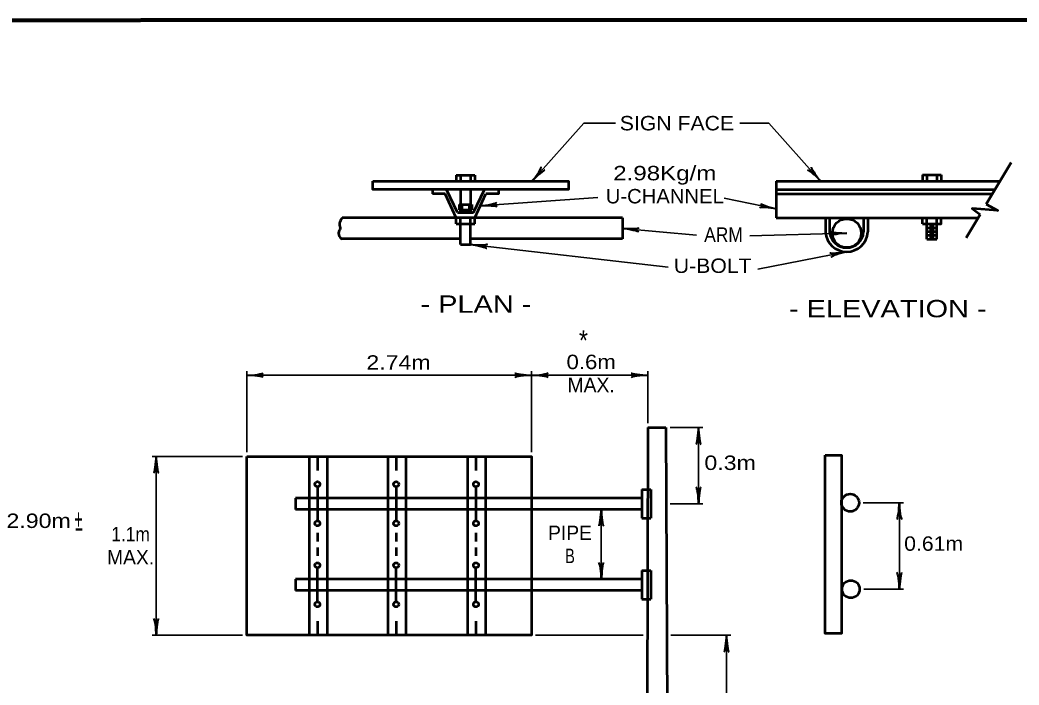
# Model space of a CAD drawing. Extents: x -274 to 582, y -298 to 246.
# Drawn here: x 154.4 to 362.2, y 101.7 to 240 of the extents above; entities that cross this region are included whole.
import ezdxf
from ezdxf.enums import TextEntityAlignment as Align

# ---------------------------------------------------------------- set-up
doc = ezdxf.new("R2010")
doc.units = 0
doc.header["$LTSCALE"] = 1.2
doc.layers.add('1', color=7, linetype='Continuous', lineweight=53)

msp = doc.modelspace()

# ---------------------------------------------------------------- linework, layer by layer
at = {"layer": '1', "lineweight": 35}
for p, q in [((271.669, 218.515), (260.903, 206.487)), ((271.669, 218.515), (278.267, 218.515)), ((304.099, 218.515), (310.143, 218.515)), ((310.143, 218.515), (320.909, 206.487)), ((250.141, 201.342), (274.617, 203.067)), ((311.68, 200.679), (300.87, 202.926)), ((279.711, 196.639), (295.114, 195.202)), ((326.39, 195.642), (306.205, 195.062)), ((248.108, 193.288), (289.218, 188.602)), ((326.35, 191.767), (307.89, 188.18)), ((201.538, 150.12), (201.538, 166.984)), ((260.772, 150.12), (260.772, 166.984)), ((284.987, 156.121), (284.987, 166.984)), ((260.772, 166.113), (201.538, 166.113)), ((260.772, 166.113), (284.987, 166.113)), ((289.606, 155.25), (296.404, 155.25)), ((295.533, 139.394), (295.533, 155.25)), ((200.667, 149.248), (181.834, 149.248)), ((182.705, 149.248), (182.705, 112.065)), ((289.606, 139.394), (296.404, 139.394)), ((329.795, 139.614), (338.185, 139.614)), ((337.314, 139.614), (337.314, 121.643)), ((275.307, 138.232), (275.307, 123.712)), ((329.919, 121.643), (338.185, 121.643)), ((200.667, 112.065), (181.834, 112.065)), ((261.643, 112.065), (283.997, 112.065)), ((289.785, 112.065), (302.229, 112.065)), ((301.358, 112.065), (301.358, 67.767))]:
    msp.add_line(p, q, dxfattribs=at)
at = {"layer": '1'}
for p, q in [((360.563, 210.368), (355.401, 201.666)), ((245.124, 207.733), (248.979, 207.733)), ((245.124, 207.733), (245.124, 206.487)), ((245.996, 207.733), (245.996, 206.487)), ((248.108, 207.733), (248.108, 206.487)), ((248.979, 207.733), (248.979, 206.487)), ((311.718, 206.487), (311.718, 198.827)), ((311.718, 206.487), (358.259, 206.487)), ((342.144, 207.762), (346, 207.762)), ((342.144, 207.762), (342.144, 206.516)), ((343.016, 207.762), (343.016, 206.487)), ((345.128, 207.762), (345.128, 206.516)), ((346, 207.762), (346, 206.516)), ((240.188, 204.708), (240.188, 203.854)), ((242.801, 203.854), (240.188, 203.854)), ((245.124, 198.83), (242.801, 203.854)), ((245.415, 199.912), (243.092, 204.708)), ((245.996, 204.708), (245.996, 201.642)), ((248.108, 204.708), (248.108, 201.642)), ((248.689, 199.912), (251.012, 204.708)), ((248.979, 198.83), (251.303, 203.854)), ((311.718, 204.708), (357.204, 204.708)), ((311.718, 203.854), (356.699, 203.854)), ((245.705, 201.642), (245.705, 200.502)), ((245.705, 201.642), (248.399, 201.642)), ((246.286, 201.642), (246.286, 200.502)), ((247.818, 201.642), (247.818, 200.502)), ((248.399, 201.642), (248.399, 200.502)), ((245.415, 199.912), (248.689, 199.912)), ((245.705, 200.502), (248.399, 200.502)), ((245.996, 200.502), (245.996, 199.912)), ((248.108, 200.502), (248.108, 199.912)), ((279.711, 198.827), (221.391, 198.827)), ((245.124, 197.584), (245.124, 198.83)), ((245.124, 197.584), (248.979, 197.584)), ((245.996, 193.288), (245.996, 198.83)), ((248.108, 193.288), (248.108, 198.83)), ((248.979, 197.584), (248.979, 198.83)), ((279.711, 198.827), (279.711, 194.45)), ((311.718, 198.827), (353.715, 198.827)), ((321.94, 198.818), (321.94, 195.907)), ((322.811, 198.818), (322.811, 195.907)), ((329.89, 198.818), (329.89, 195.907)), ((330.761, 198.818), (330.761, 195.907)), ((342.144, 197.581), (342.144, 198.827)), ((343.016, 197.581), (343.016, 198.827)), ((345.128, 194.418), (345.128, 198.827)), ((354.128, 199.522), (351.244, 194.658)), ((343.016, 196.792), (345.128, 196.792)), ((343.016, 196.001), (345.128, 196.001)), ((343.596, 197.187), (344.548, 197.187)), ((343.596, 196.398), (344.548, 196.398)), ((343.596, 195.606), (344.548, 195.606)), ((245.996, 194.45), (221.391, 194.45)), ((279.711, 194.45), (248.108, 194.45)), ((343.016, 195.21), (345.128, 195.21)), ((343.016, 194.418), (345.128, 194.418)), ((343.596, 194.815), (344.548, 194.815)), ((245.996, 193.288), (248.108, 193.288)), ((284.987, 155.25), (284.745, 67.767)), ((284.987, 155.25), (288.735, 155.25)), ((288.735, 155.25), (289.098, 67.767)), ((214.509, 149.248), (214.509, 112.065)), ((216.239, 149.248), (216.239, 146.344)), ((218.245, 149.248), (218.245, 112.065)), ((230.9, 149.248), (230.9, 112.065)), ((232.63, 149.248), (232.63, 146.344)), ((234.636, 149.248), (234.636, 112.065)), ((247.496, 149.248), (247.496, 112.065)), ((249.226, 149.248), (249.226, 146.344)), ((251.232, 149.248), (251.232, 112.065)), ((216.239, 142.92), (216.239, 135.868)), ((232.63, 142.92), (232.63, 135.868)), ((249.226, 142.92), (249.226, 135.868)), ((283.716, 142.395), (285.621, 142.395)), ((283.716, 142.395), (283.716, 136.393)), ((285.621, 142.395), (285.621, 136.393)), ((283.716, 140.556), (211.675, 140.556)), ((211.675, 140.556), (211.675, 138.232)), ((283.716, 138.232), (211.675, 138.232)), ((283.716, 136.393), (285.621, 136.393)), ((216.239, 133.337), (216.239, 131.553)), ((232.63, 133.337), (232.63, 131.553)), ((249.226, 133.337), (249.226, 131.553)), ((216.239, 130.334), (216.239, 128.608)), ((232.63, 130.334), (232.63, 128.608)), ((249.226, 130.334), (249.226, 128.608)), ((216.239, 119.025), (216.239, 126.077)), ((232.63, 119.025), (232.63, 126.077)), ((249.226, 119.025), (249.226, 126.077)), ((283.716, 125.552), (285.621, 125.552)), ((283.716, 125.552), (283.716, 119.55)), ((285.621, 125.552), (285.621, 119.55)), ((283.716, 123.712), (211.675, 123.712)), ((211.675, 123.712), (211.675, 121.389)), ((283.716, 121.389), (211.675, 121.389)), ((283.716, 119.55), (285.621, 119.55)), ((216.239, 114.969), (216.239, 112.065)), ((232.63, 114.969), (232.63, 112.065)), ((249.226, 114.969), (249.226, 112.065))]:
    msp.add_line(p, q, dxfattribs=at)
at = {"layer": '1', "lineweight": 158}
msp.add_lwpolyline([(575.293, 239.961), (-216.407, 239.861), (-216.307, -286.139)], dxfattribs=at)
at = {"layer": '1'}
for points in [[(227.749, 206.487), (268.497, 206.487), (268.497, 204.708), (227.749, 204.708)], [(201.538, 149.248), (260.772, 149.248), (260.772, 112.065), (201.538, 112.065)], [(321.86, 149.483), (325.27, 149.483), (325.27, 112.445), (321.86, 112.445)]]:
    msp.add_lwpolyline(points, close=True, dxfattribs=at)
for points in [[(253.916, 204.708), (253.916, 203.854), (251.303, 203.854)], [(355.401, 201.666), (357.773, 200.364), (352.461, 200.776), (354.128, 199.522)], [(342.144, 197.581), (346, 197.581), (346, 198.827)], [(343.016, 196.001), (343.016, 196.792), (343.016, 197.581)], [(343.016, 194.418), (343.016, 195.21), (343.016, 196.001)]]:
    msp.add_lwpolyline(points, dxfattribs=at)
for centre, radius in [((326.39, 195.641), 3.002), ((216.239, 143.46), 0.539), ((232.63, 143.46), 0.539), ((249.226, 143.46), 0.539), ((327.097, 139.614), 1.827), ((216.239, 135.328), 0.539), ((232.63, 135.328), 0.539), ((249.226, 135.328), 0.539), ((216.239, 126.616), 0.539), ((232.63, 126.616), 0.539), ((249.226, 126.616), 0.539), ((327.22, 121.643), 1.827), ((216.239, 118.485), 0.539), ((232.63, 118.485), 0.539), ((249.226, 118.485), 0.539)]:
    msp.add_circle(centre, radius, dxfattribs=at)
for radius, start, end in [(4.422, 183.66168, 356.33832), (3.55, 184.56187, 355.43813)]:
    msp.add_arc((326.35, 196.189), radius, start, end, dxfattribs=at)
at = {"layer": '1', "lineweight": 40}
for centre, major_axis, ratio, start_param, end_param in [((261.529, 207.684), (-1.289, -1.722), 0.122415, 0.8963533, 3.1415927), ((261.529, 207.684), (-1.289, -1.722), 0.122415, 0.8963533, 3.1415927), ((261.989, 207.319), (-1.563, -1.43), 0.07063, 3.1407148, 5.41811), ((261.989, 207.319), (-1.563, -1.43), 0.07063, 3.1407148, 5.41811), ((319.788, 207.241), (1.569, -1.472), 0.122415, 0.8963533, 3.1415927), ((319.788, 207.241), (1.569, -1.472), 0.122415, 0.8963533, 3.1415927), ((320.201, 207.658), (1.249, -1.711), 0.07063, 3.1407148, 5.41811), ((320.201, 207.658), (1.249, -1.711), 0.07063, 3.1407148, 5.41811), ((251.424, 201.765), (-2.124, -0.338), 0.122415, 0.8963533, 3.1415927), ((251.424, 201.765), (-2.124, -0.338), 0.122415, 0.8963533, 3.1415927), ((310.416, 201.201), (2.021, -0.635), 0.07063, 3.1407148, 5.41811), ((310.416, 201.201), (2.021, -0.635), 0.07063, 3.1407148, 5.41811), ((251.5, 201.183), (-2.117, 0.062), 0.07063, 3.1407148, 5.41811), ((251.5, 201.183), (-2.117, 0.062), 0.07063, 3.1407148, 5.41811), ((310.331, 200.621), (2.136, -0.253), 0.122415, 0.8963533, 3.1415927), ((310.331, 200.621), (2.136, -0.253), 0.122415, 0.8963533, 3.1415927), ((281.026, 196.261), (-2.079, 0.406), 0.07063, 3.1407148, 5.41811), ((281.045, 196.847), (-2.151, 0.012), 0.122415, 0.8963533, 3.1415927), ((325.039, 195.857), (2.113, -0.15), 0.07063, 3.1407148, 5.41811), ((325.039, 195.857), (2.113, -0.15), 0.07063, 3.1407148, 5.41811), ((325.091, 195.272), (2.137, 0.249), 0.122415, 0.8963533, 3.1415927), ((325.091, 195.272), (2.137, 0.249), 0.122415, 0.8963533, 3.1415927), ((249.447, 193.469), (-2.15, 0.057), 0.122415, 0.8963533, 3.1415927), ((249.447, 193.469), (-2.15, 0.057), 0.122415, 0.8963533, 3.1415927), ((249.415, 192.883), (-2.07, 0.448), 0.07063, 3.1407148, 5.41811), ((249.415, 192.883), (-2.07, 0.448), 0.07063, 3.1407148, 5.41811), ((324.982, 191.76), (2.109, 0.195), 0.07063, 3.1407148, 5.41811), ((324.982, 191.76), (2.109, 0.195), 0.07063, 3.1407148, 5.41811), ((325.128, 191.192), (2.068, 0.593), 0.122415, 0.8963533, 3.1415927), ((325.128, 191.192), (2.068, 0.593), 0.122415, 0.8963533, 3.1415927), ((202.847, 166.445), (-2.143, -0.187), 0.122415, 0.8963533, 3.1415927), ((202.847, 166.445), (-2.143, -0.187), 0.122415, 0.8963533, 3.1415927), ((259.427, 166.367), (2.108, -0.211), 0.07063, 3.1407148, 5.41811), ((259.427, 166.367), (2.108, -0.211), 0.07063, 3.1407148, 5.41811), ((262.081, 166.445), (-2.143, -0.187), 0.122415, 0.8963533, 3.1415927), ((262.081, 166.445), (-2.143, -0.187), 0.122415, 0.8963533, 3.1415927), ((283.642, 166.367), (2.108, -0.211), 0.07063, 3.1407148, 5.41811), ((283.642, 166.367), (2.108, -0.211), 0.07063, 3.1407148, 5.41811), ((202.882, 165.859), (-2.108, 0.211), 0.07063, 3.1407148, 5.41811), ((202.882, 165.859), (-2.108, 0.211), 0.07063, 3.1407148, 5.41811), ((259.463, 165.782), (2.143, 0.187), 0.122415, 0.8963533, 3.1415927), ((259.463, 165.782), (2.143, 0.187), 0.122415, 0.8963533, 3.1415927), ((262.117, 165.859), (-2.108, 0.211), 0.07063, 3.1407148, 5.41811), ((262.117, 165.859), (-2.108, 0.211), 0.07063, 3.1407148, 5.41811), ((283.677, 165.782), (2.143, 0.187), 0.122415, 0.8963533, 3.1415927), ((283.677, 165.782), (2.143, 0.187), 0.122415, 0.8963533, 3.1415927), ((295.279, 153.905), (0.211, 2.108), 0.07063, 3.1407148, 5.41811), ((295.864, 153.94), (-0.187, 2.143), 0.122415, 0.8963533, 3.1415927), ((182.451, 147.904), (0.211, 2.108), 0.07063, 3.1407148, 5.41811), ((182.451, 147.904), (0.211, 2.108), 0.07063, 3.1407148, 5.41811), ((183.037, 147.939), (-0.187, 2.143), 0.122415, 0.8963533, 3.1415927), ((183.037, 147.939), (-0.187, 2.143), 0.122415, 0.8963533, 3.1415927), ((295.201, 140.703), (0.187, -2.143), 0.122415, 0.8963533, 3.1415927), ((295.787, 140.739), (-0.211, -2.108), 0.07063, 3.1407148, 5.41811), ((337.06, 138.27), (0.211, 2.108), 0.07063, 3.1407148, 5.41811), ((337.646, 138.305), (-0.187, 2.143), 0.122415, 0.8963533, 3.1415927), ((275.053, 136.888), (0.211, 2.108), 0.07063, 3.1407148, 5.41811), ((275.638, 136.923), (-0.187, 2.143), 0.122415, 0.8963533, 3.1415927), ((274.975, 125.022), (0.187, -2.143), 0.122415, 0.8963533, 3.1415927), ((275.56, 125.057), (-0.211, -2.108), 0.07063, 3.1407148, 5.41811), ((336.983, 122.953), (0.187, -2.143), 0.122415, 0.8963533, 3.1415927), ((337.568, 122.988), (-0.211, -2.108), 0.07063, 3.1407148, 5.41811), ((182.374, 113.374), (0.187, -2.143), 0.122415, 0.8963533, 3.1415927), ((182.374, 113.374), (0.187, -2.143), 0.122415, 0.8963533, 3.1415927), ((182.959, 113.41), (-0.211, -2.108), 0.07063, 3.1407148, 5.41811), ((182.959, 113.41), (-0.211, -2.108), 0.07063, 3.1407148, 5.41811), ((301.104, 110.72), (0.211, 2.108), 0.07063, 3.1407148, 5.41811), ((301.689, 110.756), (-0.187, 2.143), 0.122415, 0.8963533, 3.1415927)]:
    msp.add_ellipse(centre, major_axis=major_axis, ratio=ratio, start_param=start_param, end_param=end_param, dxfattribs=at)
at = {"layer": '1'}
msp.add_spline([(221.391, 198.827), (221.048, 198.281), (220.844, 197.322), (220.98, 196.775), (220.707, 196.023), (220.98, 194.723), (221.391, 194.45)], degree=3, dxfattribs=at)

# ---------------------------------------------------------------- texts
for s, height, width, p in [('SIGN FACE', 3, 1.1, (291.043, 217.015)), ('2.98Kg/m', 3, 1.25, (288.516, 206.635)), ('U-CHANNEL', 3, 1.05, (288.516, 201.835)), ('ARM', 3, 0.9, (300.73, 193.843)), ('U-BOLT', 3, 1.1, (298.484, 187.382)), ('*', 4.2, 0.85, (271.592, 171.276)), ('2.74m', 3, 1.2, (233.114, 167.269)), ('0.6m', 3, 1.15, (273.194, 167.387)), ('0.3m', 3, 1.2, (302.105, 146.422)), ('2.90m', 3, 1.2, (158.235, 134.364)), ('+', 4.2, 0.55, (166.539, 134.103)), ('1.1m', 3, 0.9, (177.372, 131.578)), ('0.61m', 3, 1.1, (344.451, 129.62)), ('B', 3, 0.75, (268.795, 127.057))]:
    msp.add_text(s, height=height, dxfattribs=dict(at, width=width)).set_placement(p, align=Align.CENTER)
at = {"layer": '1', "width": 1.25}
for s, p in [('- PLAN -', (237.687, 179.103)), ('- ELEVATION -', (314.343, 178.168))]:
    msp.add_text(s, height=3.6, dxfattribs=at).set_placement(p)
at = {"layer": '1'}
for s, height, p in [('MAX.', 3, (273.194, 162.587)), ('-', 4.2, (166.627, 132.428)), ('PIPE', 3, (268.795, 131.857)), ('MAX.', 3, (177.372, 126.778))]:
    msp.add_text(s, height=height, dxfattribs=at).set_placement(p, align=Align.CENTER)

doc.saveas('drawing.dxf')
